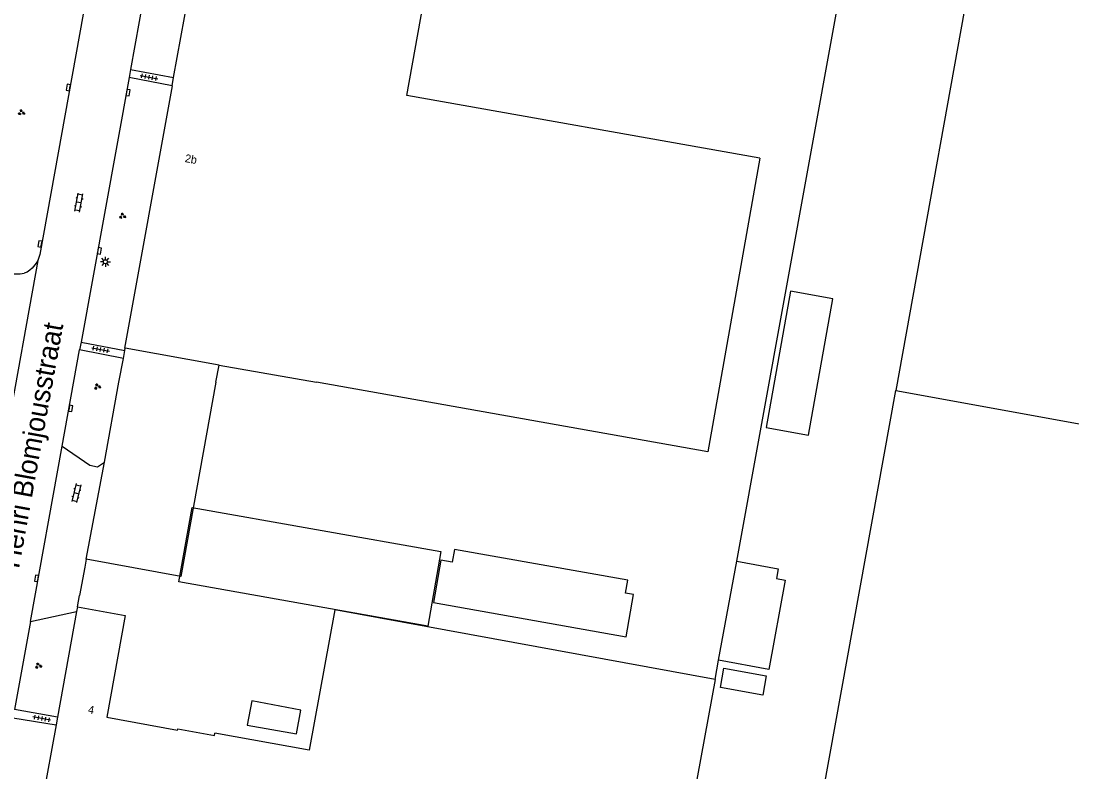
# Model space of a CAD drawing. Extents: x 130998 to 133001, y 398999 to 403002.
# Drawn here: x 132201.3 to 132332.6, y 399451.3 to 399545.1 of the extents above; entities that cross this region are included whole.
import ezdxf

# ---------------------------------------------------------------- set-up
doc = ezdxf.new("R2010")
doc.units = 0
for name, color, linetype in [('gg-afsc-erfafscheiding', 7, 'Continuous'), ('gg-afsc-muur', 7, 'Continuous'), ('gg-anno-huisnummerreeks BGT', 7, 'Continuous'), ('gg-anno-openbare ruimte label', 7, 'Continuous'), ('gg-bbg-bijgebouw', 7, 'Continuous'), ('gg-bbg-gedigitaliseerde bebouwing', 7, 'Continuous'), ('gg-bbg-gedigitaliseerde bijgebouw', 7, 'Continuous'), ('gg-bbg-hoofdgebouw', 7, 'Continuous'), ('gg-bbg-luifel en loopbrug', 7, 'Continuous'), ('gg-bbg-tussenscheiding', 7, 'Continuous'), ('gg-knt-verharding', 7, 'Continuous'), ('gg-knt-verharding nz', 7, 'Continuous'), ('gt-grn-vlakafsluiter', 7, 'Continuous'), ('gt-grn-weggrens', 7, 'Continuous'), ('gt-symb-groenvak', 7, 'Continuous'), ('gt-symb-klinker verharding', 7, 'Continuous'), ('gt-symb-kolk', 7, 'Continuous'), ('gt-symb-lichtmast', 7, 'Continuous'), ('gt-symb-tegel verharding', 7, 'Continuous')]:
    doc.layers.add(name, color=color, linetype=linetype)

# ---------------------------------------------------------------- blocks, each defined once
blk = doc.blocks.new('gt0-GRVAK')
at = {"layer": 'gt-symb-groenvak'}
for p, q in [((-0.11, 0.19), (-0.23, 0.24)), ((-0.18, 0.15), (0.09, 0.15)), ((-0.09, 0.21), (-0.16, 0.32)), ((-0.05, 0.21), (-0.05, 0.39)), ((0, 0.21), (0.06, 0.32)), ((0.01, 0.19), (0.13, 0.24)), ((0.26, -0.05), (0.2, 0.06)), ((0.3, -0.05), (0.3, 0.13)), ((0.35, -0.05), (0.41, 0.06)), ((-0.24, -0.23), (-0.36, -0.18)), ((-0.32, -0.26), (-0.05, -0.26)), ((-0.23, -0.21), (-0.29, -0.09)), ((-0.18, -0.2), (-0.18, -0.02)), ((-0.14, -0.21), (-0.07, -0.09)), ((-0.12, -0.23), (0, -0.18)), ((0.24, -0.07), (0.12, -0.02)), ((0.17, -0.11), (0.44, -0.11)), ((0.37, -0.07), (0.49, -0.02))]:
    blk.add_line(p, q, dxfattribs=at)
blk = doc.blocks.new('gt0-KOLK')
at = {"layer": 'gt-symb-kolk'}
blk.add_lwpolyline([(0, 0), (0.37, 0), (0.37, 0.4), (-0.38, 0.4), (-0.38, 0), (0, 0)], dxfattribs=at)
blk = doc.blocks.new('gt0-TEG1')
at = {"layer": 'gt-symb-tegel verharding'}
for p, q in [((-1.12, 0), (1.12, 0)), ((-0.9, -0.25), (-0.9, 0.25)), ((-0.45, -0.25), (-0.45, 0.25)), ((0, -0.25), (0, 0.25)), ((0.45, -0.25), (0.45, 0.25)), ((0.9, -0.25), (0.9, 0.25))]:
    blk.add_line(p, q, dxfattribs=at)
blk = doc.blocks.new('gt0-KL1')
at = {"layer": 'gt-symb-klinker verharding'}
for p, q in [((-1.15, 0.3), (1.15, 0.3)), ((-1, -0.3), (-1, 0.3)), ((-0.5, 0.3), (-0.5, 0.45)), ((0, -0.3), (0, 0.3)), ((0.5, 0.3), (0.5, 0.45)), ((1, -0.3), (1, 0.3)), ((-1.15, -0.3), (1.15, -0.3)), ((-0.5, -0.45), (-0.5, -0.3)), ((0.5, -0.45), (0.5, -0.3))]:
    blk.add_line(p, q, dxfattribs=at)
blk = doc.blocks.new('gt0-LMAST')
at = {"layer": 'gt-symb-lichtmast'}
for p, q in [((-0.18, 0.17), (-0.45, 0.44)), ((-0.01, 0.25), (-0.01, 0.62)), ((0.17, 0.17), (0.44, 0.44)), ((-0.26, 0), (-0.63, 0)), ((-0.18, -0.18), (-0.45, -0.45)), ((-0.01, -0.25), (-0.01, -0.63)), ((0.44, -0.45), (0.17, -0.18)), ((0.24, 0), (0.62, 0))]:
    blk.add_line(p, q, dxfattribs=at)
blk.add_circle((-0.01, 0), 0.25, dxfattribs=at)

msp = doc.modelspace()

# ---------------------------------------------------------------- linework, layer by layer
at = {"layer": 'gg-afsc-erfafscheiding'}
msp.add_line((132225.64, 399500), (132226.03, 399502.13), dxfattribs=at)
msp.add_lwpolyline([(132225.64, 399500), (132221.24, 399475.77), (132212.38, 399477.38)], dxfattribs=at)
at = {"layer": 'gg-afsc-muur'}
for p, q in [((132290.7, 399477.67), (132302.95, 399545.04)), ((132209.43, 399477.92), (132209.25, 399476.9)), ((132212.38, 399477.38), (132209.43, 399477.92)), ((132208.35, 399471.96), (132208.61, 399473.39)), ((132287.99, 399462.9), (132288.43, 399465.3))]:
    msp.add_line(p, q, dxfattribs=at)
at = {"layer": 'gg-bbg-bijgebouw'}
msp.add_lwpolyline([(132290.7, 399477.67), (132295.87, 399476.72), (132295.65, 399475.49), (132296.73, 399475.29), (132294.68, 399464.15), (132288.43, 399465.3)], dxfattribs=at)
at = {"layer": 'gg-bbg-gedigitaliseerde bebouwing'}
for p, q in [((132226.03, 399502.13), (132238.21, 399500)), ((132208.35, 399471.96), (132214.3, 399470.88)), ((132287.99, 399462.9), (132282.54, 399432.98)), ((132237.27, 399454.05), (132225.52, 399456.21))]:
    msp.add_line(p, q, dxfattribs=at)
for points in [[(132293.59, 399527.96), (132287.08, 399491.3), (132238.21, 399500)], [(132287.99, 399462.9), (132240.48, 399471.57), (132237.27, 399454.05)], [(132214.3, 399470.88), (132212, 399458.18), (132220.85, 399456.57), (132220.88, 399456.73)], [(132220.88, 399456.73), (132225.46, 399455.89), (132225.52, 399456.21)]]:
    msp.add_lwpolyline(points, dxfattribs=at)
at = {"layer": 'gg-bbg-gedigitaliseerde bijgebouw'}
msp.add_line((132288.43, 399465.3), (132290.7, 399477.67), dxfattribs=at)
for points in [[(132289.09, 399464.29), (132294.37, 399463.35), (132293.94, 399460.94), (132288.66, 399461.88), (132289.09, 399464.29)], [(132229.55, 399457.2), (132235.71, 399456.11), (132236.24, 399459.08), (132230.11, 399460.21), (132229.55, 399457.2)]]:
    msp.add_lwpolyline(points, dxfattribs=at)
at = {"layer": 'gg-bbg-hoofdgebouw'}
for p, q in [((132220.36, 399538.04), (132223, 399552.56)), ((132220.17, 399537), (132220.36, 399538.04)), ((132226.03, 399502.13), (132214.32, 399504.25)), ((132208.24, 399471.38), (132205.85, 399458.18)), ((132208.35, 399471.96), (132208.24, 399471.38)), ((132205.85, 399458.18), (132205.67, 399457.22))]:
    msp.add_line(p, q, dxfattribs=at)
for points in [[(132405.32, 399543.29), (132321.27, 399558.35), (132310.54, 399498.95)], [(132293.59, 399527.96), (132249.47, 399535.8), (132251.58, 399547.36)], [(132220.17, 399537), (132214.21, 399504.27), (132214.32, 399504.25)], [(132347.49, 399446.62), (132342.33, 399447.55), (132340.53, 399437.68), (132300.77, 399444.91), (132310.54, 399498.95)], [(132205.67, 399457.22), (132203.98, 399447.92), (132209.15, 399446.98), (132209.07, 399446.44), (132221.31, 399444.2)]]:
    msp.add_lwpolyline(points, dxfattribs=at)
at = {"layer": 'gg-bbg-luifel en loopbrug'}
for points in [[(132297.4, 399511.37), (132294.37, 399494.33), (132299.66, 399493.39), (132302.69, 399510.43), (132297.4, 399511.37)], [(132222.69, 399484.38), (132253.75, 399478.86), (132252.1, 399469.57), (132221.03, 399475.09), (132222.69, 399484.38)], [(132252.8, 399472.49), (132276.86, 399468.21), (132277.8, 399473.51), (132276.79, 399473.68), (132277.08, 399475.28), (132255.43, 399479.13), (132255.15, 399477.54), (132253.75, 399477.79), (132252.8, 399472.49)]]:
    msp.add_lwpolyline(points, dxfattribs=at)
at = {"layer": 'gg-bbg-tussenscheiding'}
msp.add_line((132310.54, 399498.95), (132407.05, 399481.51), dxfattribs=at)
at = {"layer": 'gg-knt-verharding'}
for p, q in [((132217.18, 399551.16), (132214.98, 399539.03)), ((132214.8, 399538.04), (132208.8, 399505.01)), ((132214.98, 399539.03), (132214.8, 399538.04)), ((132220.17, 399537), (132214.8, 399538.04)), ((132214.98, 399539.03), (132220.36, 399538.04)), ((132206.43, 399492), (132208.62, 399504.03)), ((132208.8, 399505.01), (132208.62, 399504.03)), ((132214.08, 399502.96), (132208.62, 399504.03)), ((132208.8, 399505.01), (132214.26, 399503.98)), ((132214.08, 399502.96), (132214.26, 399503.98)), ((132214.26, 399503.98), (132214.32, 399504.25)), ((132209.25, 399476.9), (132208.61, 399473.39)), ((132202.47, 399470.15), (132208.24, 399471.38)), ((132202.47, 399470.15), (132200.47, 399459.13)), ((132200.28, 399458.12), (132205.67, 399457.22)), ((132205.85, 399458.18), (132200.47, 399459.13))]:
    msp.add_line(p, q, dxfattribs=at)
for points in [[(132209.07, 399545.93), (132203.63, 399515.95), (132203.39, 399515.2)], [(132203.39, 399515.2), (132203.19, 399514.86), (132202.7, 399514.25), (132202.41, 399513.98), (132202.07, 399513.76), (132201.7, 399513.63)], [(132211.71, 399490.04), (132213.52, 399500), (132214.08, 399502.96)], [(132206.43, 399492), (132209.89, 399489.63), (132210.84, 399489.42), (132211.71, 399490.04)]]:
    msp.add_lwpolyline(points, dxfattribs=at)
msp.add_arc((132200.72, 399518.07), 4.55, 256.6332, 282.4645, dxfattribs=at)
at = {"layer": 'gg-knt-verharding nz'}
for p, q in [((132203.39, 399515.2), (132199.44, 399493.21)), ((132202.47, 399470.15), (132206.43, 399492))]:
    msp.add_line(p, q, dxfattribs=at)
at = {"layer": 'gt-grn-vlakafsluiter'}
msp.add_line((132302.95, 399545.04), (132306.36, 399563.93), dxfattribs=at)
at = {"layer": 'gt-grn-weggrens'}
msp.add_line((132209.43, 399477.92), (132211.71, 399490.04), dxfattribs=at)

# ---------------------------------------------------------------- block references
at = {"layer": 'gt-symb-groenvak', "rotation": -10.30997039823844}
for p in [(132201.33, 399533.67), (132213.97, 399520.75)]:
    msp.add_blockref('gt0-GRVAK', p, dxfattribs=at)
at = {"layer": 'gt-symb-groenvak'}
for p in [(132210.83, 399499.45), (132203.46, 399464.6)]:
    msp.add_blockref('gt0-GRVAK', p, dxfattribs=at)
at = {"layer": 'gt-symb-klinker verharding'}
for p, rotation in [((132208.53, 399522.43), 79.69002960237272), ((132208.21, 399486.16), -103.93901435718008)]:
    msp.add_blockref('gt0-KL1', p, dxfattribs=dict(at, rotation=rotation))
at = {"layer": 'gt-symb-kolk'}
for p, rotation in [((132207.41, 399536.76), 79.63367739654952), ((132214.46, 399536.18), -100.25359802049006), ((132203.86, 399517.23), 79.80279442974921), ((132210.88, 399516.44), -100.30997039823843), ((132207.3, 399496.77), -99.84862238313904), ((132203.43, 399475.49), 79.92566727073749)]:
    msp.add_blockref('gt0-KOLK', p, dxfattribs=dict(at, rotation=rotation))
at = {"layer": 'gt-symb-lichtmast'}
msp.add_blockref('gt0-LMAST', (132211.84, 399515.04), dxfattribs=at)
at = {"layer": 'gt-symb-tegel verharding'}
for p, rotation in [((132217.29, 399538.08), -10.950434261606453), ((132211.24, 399504.09), -11.13011108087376), ((132203.88, 399458.02), 170.0384834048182)]:
    msp.add_blockref('gt0-TEG1', p, dxfattribs=dict(at, rotation=rotation))

# ---------------------------------------------------------------- texts
at = {"layer": 'gg-anno-huisnummerreeks BGT'}
for s, p in [('2b', (132221.71, 399527.5)), ('4', (132209.61, 399458.69))]:
    msp.add_text(s, height=1, rotation=349.7, dxfattribs=at).set_placement(p)
at = {"layer": 'gg-anno-openbare ruimte label'}
msp.add_text('Henri Blomjousstraat', height=2.5, rotation=79.7, dxfattribs=at).set_placement((132201.04, 399476.65))

doc.saveas('drawing.dxf')
